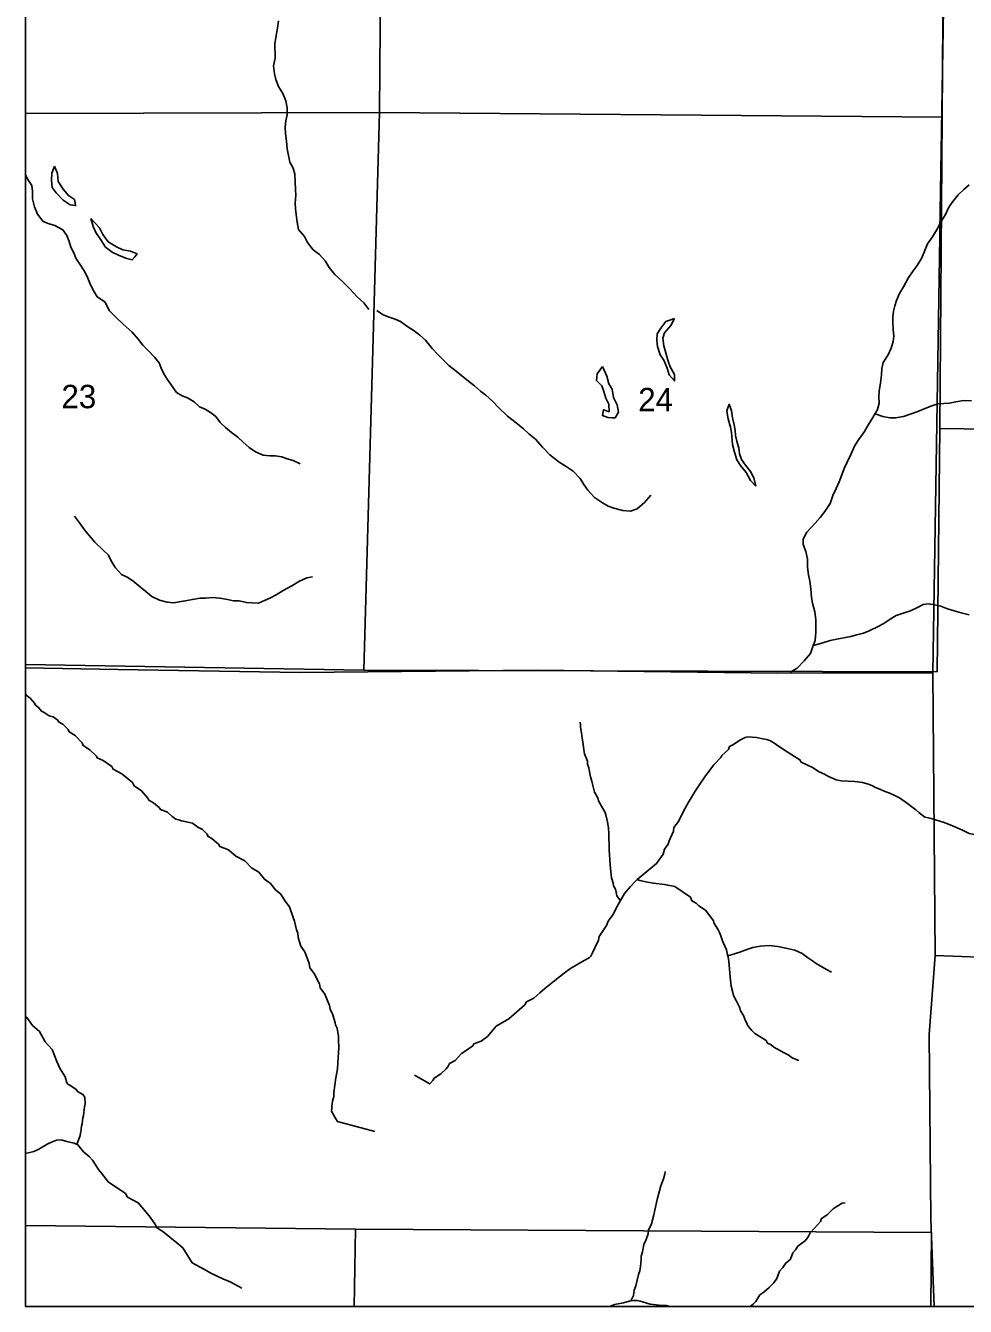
# Model space of a CAD drawing. Extents: x -10 to 158, y 8 to 33.
# Drawn here: x -9.564 to -7.882, y 8.322 to 10.614 of the extents above; entities that cross this region are included whole.
import ezdxf

# ---------------------------------------------------------------- set-up
doc = ezdxf.new("R2010")
doc.units = 0
for name, color, linetype in [('GM_X_Corporation', 7, 'Continuous'), ('GM_X_Minor_Lake', 7, 'Continuous'), ('GM_X_Minor_River', 7, 'Continuous'), ('GM_X_Section_Text', 7, 'Continuous')]:
    doc.layers.add(name, color=color, linetype=linetype)

msp = doc.modelspace()

# ---------------------------------------------------------------- linework, layer by layer
at = {"layer": 'GM_X_Corporation'}
for points in [[(-3.9824, 15.1217), (-9.5644, 15.1217), (-9.5644, 9.4643), (-9.3995, 9.4613), (-9.0726, 9.4561), (-8.6489, 9.4603), (-8.2177, 9.4548), (-7.9405, 9.4552), (-7.9359, 8.9497), (-7.8105, 8.9446), (-6.576, 8.9279), (-5.6716, 8.9116)], [(-3.9824, 15.1217), (-7.9061, 15.1217), (-7.9061, 14.9456), (-7.9061, 14.9432), (-7.9044, 14.3264), (-7.9089, 13.4536), (-7.9163, 10.9342), (-7.9163, 10.9333), (-7.9276, 10.245), (-7.9277, 10.2365), (-7.9405, 9.4552), (-7.9359, 8.9497), (-7.8105, 8.9446), (-6.576, 8.9279), (-5.6716, 8.9116)]]:
    msp.add_lwpolyline(points, dxfattribs=at)
for points in [[(-7.9061, 15.1217), (-9.5644, 15.1217), (-9.5644, 9.4643), (-9.3995, 9.4613), (-9.0726, 9.4561), (-8.6489, 9.4603), (-8.2177, 9.4548), (-7.9405, 9.4552), (-7.9277, 10.2365), (-7.9276, 10.245), (-7.9163, 10.9333), (-7.9163, 10.9342), (-7.9089, 13.4536), (-7.9044, 14.3264), (-7.9061, 14.9432), (-7.9061, 14.9456)], [(-9.5644, 11.46), (-9.5644, 10.4563), (-8.9307, 10.4584), (-8.9234, 11.4538)], [(-7.9172, 11.45), (-7.9205, 10.8845), (-7.9238, 10.4498), (-8.9307, 10.4584), (-8.9234, 11.4538)], [(-7.0512, 10.8902), (-7.0611, 9.881), (-7.9279, 9.893), (-7.9238, 10.4498), (-7.9205, 10.8845)], [(-9.5644, 10.4563), (-9.5644, 9.4706), (-8.9587, 9.4604), (-8.9307, 10.4584)], [(-7.9238, 10.4498), (-7.9279, 9.893), (-7.9324, 9.4573), (-8.9587, 9.4604), (-8.9307, 10.4584)], [(-9.5644, 9.4643), (-9.5644, 8.3217), (-3.0592, 8.3217), (-3.0461, 8.849), (-3.0384, 9.32), (-3.038, 9.8353), (-3.5382, 9.8396), (-4.0418, 9.845), (-4.0443, 9.3749), (-4.0456, 9.0756), (-4.0474, 8.8852), (-4.2975, 8.8883), (-4.8083, 8.897), (-5.5966, 8.9104), (-5.6716, 8.9116), (-6.576, 8.9279), (-7.8105, 8.9446), (-7.9359, 8.9497), (-7.9405, 9.4552), (-8.2177, 9.4548), (-8.6489, 9.4603), (-9.0726, 9.4561), (-9.3995, 9.4613)], [(-7.9379, 8.3217), (-3.0592, 8.3217), (-3.0461, 8.849), (-3.0384, 9.32), (-3.038, 9.8353), (-3.5382, 9.8396), (-4.0418, 9.845), (-4.0443, 9.3749), (-4.0456, 9.0756), (-4.0474, 8.8852), (-4.2975, 8.8883), (-4.8083, 8.897), (-5.5966, 8.9104), (-5.6716, 8.9116), (-6.576, 8.9279), (-7.8105, 8.9446), (-7.9359, 8.9497), (-7.947, 8.8081), (-7.9441, 8.4785)], [(-9.5644, 9.4643), (-9.5644, 8.3217), (-7.9379, 8.3217), (-7.9441, 8.4785), (-7.947, 8.8081), (-7.9359, 8.9497), (-7.9405, 9.4552), (-8.2177, 9.4548), (-8.6489, 9.4603), (-9.0726, 9.4561), (-9.3995, 9.4613)], [(-9.5644, 8.4667), (-9.5644, 8.3217), (-8.9763, 8.3217), (-8.9739, 8.4602)], [(-8.9763, 8.3217), (-7.9439, 8.3217), (-7.9427, 8.454), (-8.9739, 8.4602)]]:
    msp.add_lwpolyline(points, close=True, dxfattribs=at)
at = {"layer": 'GM_X_Minor_Lake'}
for points in [[(-9.5126, 10.3624), (-9.5174, 10.3494), (-9.518, 10.3373), (-9.5171, 10.324), (-9.5098, 10.3142), (-9.4971, 10.3015), (-9.4845, 10.2929), (-9.475, 10.2915), (-9.4758, 10.2963)], [(-9.4758, 10.2963), (-9.4767, 10.3025), (-9.4878, 10.3096), (-9.4974, 10.3212), (-9.5062, 10.3348), (-9.5072, 10.3488), (-9.5126, 10.3624)], [(-9.4479, 10.2683), (-9.4435, 10.2543), (-9.4389, 10.2437), (-9.43, 10.2301), (-9.4211, 10.2173), (-9.4096, 10.208), (-9.3967, 10.2021), (-9.3834, 10.1969), (-9.3735, 10.1943), (-9.3688, 10.2001)], [(-9.3688, 10.2001), (-9.3649, 10.2051), (-9.3767, 10.2099), (-9.3904, 10.2124), (-9.4018, 10.2179), (-9.4163, 10.2269), (-9.4259, 10.2397), (-9.4321, 10.2521), (-9.4479, 10.2683)], [(-8.4025, 10.0898), (-8.418, 10.0839), (-8.4273, 10.0724), (-8.434, 10.0624), (-8.4342, 10.0503), (-8.4333, 10.0393), (-8.4282, 10.0245), (-8.4216, 10.0147), (-8.4161, 10.0004), (-8.4126, 9.989), (-8.4029, 9.9778), (-8.4028, 9.9857)], [(-8.4028, 9.9857), (-8.4027, 9.9895), (-8.4108, 10.0031), (-8.4148, 10.0152), (-8.4184, 10.0284), (-8.422, 10.0409), (-8.4237, 10.0542), (-8.4204, 10.0637), (-8.4092, 10.0768), (-8.4025, 10.0898)], [(-8.5315, 10.0038), (-8.5412, 9.9908), (-8.5426, 9.9786), (-8.5326, 9.9693), (-8.529, 9.959), (-8.5258, 9.9469), (-8.5204, 9.936), (-8.5198, 9.9227), (-8.5297, 9.9264), (-8.5319, 9.9157), (-8.522, 9.9121), (-8.5145, 9.9117)], [(-8.5145, 9.9117), (-8.509, 9.9115), (-8.5031, 9.9218), (-8.5052, 9.9351), (-8.5118, 9.9479), (-8.5143, 9.963), (-8.5205, 9.9728), (-8.5241, 9.9861), (-8.5315, 10.0038)], [(-8.3076, 9.9278), (-8.3089, 9.9239), (-8.3068, 9.9099), (-8.3024, 9.8948), (-8.3008, 9.8853), (-8.299, 9.8641), (-8.2954, 9.8501), (-8.291, 9.8364), (-8.2848, 9.8267), (-8.2744, 9.8139), (-8.2667, 9.7999), (-8.2574, 9.7898)], [(-8.2574, 9.7898), (-8.261, 9.8042), (-8.2665, 9.8155), (-8.2757, 9.8272), (-8.2827, 9.8373), (-8.2863, 9.8471), (-8.2875, 9.8574), (-8.2911, 9.8699), (-8.2935, 9.8801), (-8.2944, 9.8899), (-8.296, 9.8994), (-8.2989, 9.9115), (-8.3009, 9.9244), (-8.3049, 9.9361), (-8.3076, 9.9278)]]:
    msp.add_lwpolyline(points, dxfattribs=at)
at = {"layer": 'GM_X_Minor_River'}
for points in [[(-8.9497, 10.1058), (-8.959, 10.1173), (-8.9709, 10.1286), (-8.9839, 10.1425), (-8.9966, 10.1552), (-9.0111, 10.1683), (-9.0208, 10.1811), (-9.0281, 10.1928), (-9.0385, 10.2041), (-9.0496, 10.2123), (-9.0599, 10.2258), (-9.0654, 10.2364), (-9.0758, 10.2488), (-9.0782, 10.2621), (-9.0802, 10.2757), (-9.0811, 10.2859), (-9.0816, 10.2962), (-9.0806, 10.3102), (-9.0815, 10.3201), (-9.0817, 10.3349), (-9.0826, 10.3481), (-9.0857, 10.3587), (-9.0911, 10.3693), (-9.0936, 10.381), (-9.096, 10.3931), (-9.0973, 10.4071), (-9.0989, 10.4204), (-9.0998, 10.4318), (-9.0984, 10.4432), (-9.0963, 10.4538), (-9.096, 10.4663), (-9.0985, 10.4792), (-9.1039, 10.4924), (-9.1116, 10.5049), (-9.1167, 10.5173), (-9.1191, 10.5272), (-9.1204, 10.5416), (-9.1179, 10.5556), (-9.1182, 10.581), (-9.1157, 10.5959), (-9.1136, 10.6092), (-9.1118, 10.6221)], [(-9.0726, 9.8296), (-9.0855, 9.8352), (-9.0961, 9.8385), (-9.1056, 9.8418), (-9.1174, 9.844), (-9.1269, 9.8439), (-9.139, 9.8449), (-9.1527, 9.8508), (-9.1642, 9.859), (-9.1749, 9.868), (-9.1845, 9.877), (-9.196, 9.8856), (-9.2063, 9.8942), (-9.2159, 9.9032), (-9.2236, 9.9141), (-9.2331, 9.9212), (-9.2431, 9.9272), (-9.2533, 9.9316), (-9.2629, 9.9406), (-9.2744, 9.9473), (-9.2843, 9.951), (-9.2942, 9.957), (-9.3008, 9.9668), (-9.3108, 9.9807), (-9.3169, 9.9905), (-9.3216, 10.0007), (-9.3251, 10.0105), (-9.3336, 10.0203), (-9.3443, 10.0319), (-9.3543, 10.0417), (-9.3624, 10.0518), (-9.3739, 10.065), (-9.39, 10.0792), (-9.4015, 10.0909), (-9.4145, 10.1032), (-9.4227, 10.1195), (-9.436, 10.1284), (-9.4422, 10.1382), (-9.4484, 10.1499), (-9.4543, 10.165), (-9.4597, 10.1748), (-9.4659, 10.185), (-9.4744, 10.1974), (-9.4783, 10.2072), (-9.4833, 10.217), (-9.4864, 10.2273), (-9.4904, 10.2382), (-9.4977, 10.248), (-9.5118, 10.2558), (-9.5221, 10.2587), (-9.5327, 10.2632), (-9.5431, 10.2763), (-9.5482, 10.2896), (-9.5518, 10.3039), (-9.5519, 10.3176), (-9.5535, 10.3278), (-9.5605, 10.338), (-9.5644, 10.346)], [(-8.1956, 9.4569), (-8.1833, 9.4638), (-8.1706, 9.4769), (-8.1594, 9.4903), (-8.155, 9.5025), (-8.151, 9.5132), (-8.1497, 9.5284), (-8.15, 9.5512), (-8.1516, 9.5649), (-8.1556, 9.58), (-8.1577, 9.5902), (-8.159, 9.6058), (-8.1607, 9.6194), (-8.1628, 9.6308), (-8.1645, 9.6444), (-8.1646, 9.6589), (-8.1679, 9.6725), (-8.1722, 9.685), (-8.1727, 9.6948), (-8.1657, 9.7074), (-8.1511, 9.7232), (-8.1421, 9.7336), (-8.1335, 9.7443), (-8.1242, 9.7585), (-8.1191, 9.773), (-8.1136, 9.7856), (-8.1077, 9.7974), (-8.1033, 9.81), (-8.0989, 9.8211), (-8.0944, 9.8314), (-8.0871, 9.8463), (-8.0797, 9.862), (-8.0734, 9.8723), (-8.0629, 9.8872), (-8.0574, 9.8968), (-8.0477, 9.9121), (-8.0392, 9.9267), (-8.0363, 9.9381), (-8.0368, 9.9495), (-8.0366, 9.9594), (-8.0337, 9.9746), (-8.0324, 9.989), (-8.0318, 10), (-8.0293, 10.0107), (-8.0203, 10.0245), (-8.0148, 10.0363), (-8.0115, 10.0482), (-8.0102, 10.0577), (-8.0111, 10.0702), (-8.012, 10.0823), (-8.0117, 10.0922), (-8.0107, 10.1025), (-8.0082, 10.112), (-8.0053, 10.1219), (-7.9998, 10.1341), (-7.9927, 10.146), (-7.9846, 10.1617), (-7.9753, 10.1747), (-7.9686, 10.1843), (-7.96, 10.1984), (-7.9549, 10.2114), (-7.9501, 10.2229), (-7.9408, 10.2359), (-7.9319, 10.2508), (-7.926, 10.2627), (-7.9185, 10.2745), (-7.9115, 10.289), (-7.9044, 10.299), (-7.8947, 10.3109), (-7.885, 10.3205), (-7.8752, 10.329)], [(-8.9357, 10.104), (-8.9254, 10.0967), (-8.9155, 10.0926), (-8.9029, 10.0882), (-8.8934, 10.0842), (-8.8804, 10.0749), (-8.8708, 10.0689), (-8.8585, 10.06), (-8.8485, 10.0506), (-8.8366, 10.0359), (-8.8266, 10.0251), (-8.8066, 10.0056), (-8.7939, 9.9955), (-8.7832, 9.9869), (-8.7717, 9.9775), (-8.761, 9.9693), (-8.7502, 9.9596), (-8.7406, 9.9525), (-8.728, 9.9409), (-8.7187, 9.9311), (-8.7015, 9.9147), (-8.6865, 9.9031), (-8.6731, 9.8919), (-8.6635, 9.8833), (-8.6516, 9.8735), (-8.6393, 9.8593), (-8.6262, 9.8458), (-8.6093, 9.8327), (-8.5982, 9.826), (-8.5841, 9.8163), (-8.5717, 9.8032), (-8.5652, 9.7923), (-8.5578, 9.7825), (-8.5459, 9.769), (-8.5317, 9.7597), (-8.5214, 9.7537), (-8.5115, 9.7501), (-8.4955, 9.7461), (-8.4814, 9.7447), (-8.4694, 9.7487), (-8.4566, 9.7603), (-8.445, 9.7737)], [(-8.0437, 9.9189), (-8.0299, 9.9139), (-8.0173, 9.9118), (-8.0071, 9.9115), (-7.9927, 9.914), (-7.981, 9.9183), (-7.9674, 9.923), (-7.9531, 9.9289), (-7.9421, 9.9332), (-7.9315, 9.9368), (-7.9209, 9.9373), (-7.9103, 9.9382), (-7.899, 9.9406), (-7.8853, 9.9427), (-7.8709, 9.9421)], [(-9.051, 9.6271), (-9.0607, 9.6253), (-9.0739, 9.6195), (-9.0878, 9.6114), (-9.1033, 9.6029), (-9.1157, 9.5951), (-9.127, 9.5893), (-9.1368, 9.5847), (-9.1474, 9.5804), (-9.1591, 9.5806), (-9.169, 9.5813), (-9.1823, 9.5842), (-9.1922, 9.5844), (-9.2032, 9.5866), (-9.2165, 9.5891), (-9.2298, 9.5905), (-9.2423, 9.5892), (-9.2517, 9.5891), (-9.2657, 9.587), (-9.2786, 9.5842), (-9.2892, 9.5826), (-9.299, 9.5806), (-9.3108, 9.582), (-9.3245, 9.5853), (-9.3386, 9.5919), (-9.3489, 9.6009), (-9.3585, 9.6088), (-9.3726, 9.62), (-9.3826, 9.6264), (-9.3925, 9.6312), (-9.4032, 9.6432), (-9.4106, 9.6549), (-9.416, 9.6658), (-9.4263, 9.6756), (-9.4405, 9.6891), (-9.4505, 9.7011), (-9.459, 9.7116), (-9.4682, 9.7241), (-9.4767, 9.7361)], [(-8.1542, 9.5046), (-8.1357, 9.5096), (-8.124, 9.5132), (-8.1093, 9.5164), (-8.0968, 9.5189), (-8.0869, 9.5205), (-8.0764, 9.5233), (-8.0646, 9.5265), (-8.0544, 9.5304), (-8.0394, 9.5375), (-8.0281, 9.5437), (-8.0164, 9.5518), (-8.0062, 9.558), (-7.9919, 9.5628), (-7.9802, 9.5667), (-7.9677, 9.5726), (-7.9576, 9.578), (-7.9481, 9.5789), (-7.9367, 9.5771), (-7.926, 9.5746), (-7.9142, 9.5702), (-7.902, 9.5662), (-7.8895, 9.5626), (-7.875, 9.5593)], [(-8.9392, 8.6344), (-9.006, 8.6523), (-9.0106, 8.6606), (-9.017, 8.6708), (-9.0164, 8.6765), (-9.0164, 8.6796), (-9.0151, 8.6887), (-9.0129, 8.6975), (-9.0127, 8.7047), (-9.009, 8.731), (-9.0058, 8.747), (-9.0056, 8.7576), (-9.0038, 8.785), (-9.004, 8.7979), (-9.0045, 8.8048), (-9.0067, 8.8195), (-9.0095, 8.8256), (-9.0103, 8.829), (-9.0143, 8.8434), (-9.019, 8.8535), (-9.0203, 8.8604), (-9.0286, 8.8807), (-9.0372, 8.892), (-9.0384, 8.8992), (-9.0479, 8.9173), (-9.0556, 8.9278), (-9.0569, 8.9354), (-9.0645, 8.9562), (-9.0715, 8.9663), (-9.0763, 8.9818), (-9.0772, 8.9898), (-9.0792, 8.9958), (-9.0829, 9.011), (-9.0853, 9.0174), (-9.0921, 9.037), (-9.0998, 9.0468), (-9.1073, 9.0596), (-9.1173, 9.0674), (-9.1258, 9.0787), (-9.137, 9.0861), (-9.147, 9.0988), (-9.1601, 9.1066), (-9.1721, 9.119), (-9.1882, 9.1271), (-9.2009, 9.1387), (-9.2169, 9.1449), (-9.2189, 9.1486), (-9.2305, 9.1583), (-9.2381, 9.1631), (-9.2393, 9.1665), (-9.2475, 9.1751), (-9.2559, 9.1792), (-9.2655, 9.1863), (-9.2823, 9.1902), (-9.2857, 9.1905), (-9.2884, 9.1916), (-9.2952, 9.1938), (-9.3021, 9.1986), (-9.3102, 9.2064), (-9.3232, 9.2112), (-9.3252, 9.2142), (-9.3356, 9.2228), (-9.344, 9.2276), (-9.3456, 9.231), (-9.3572, 9.2445), (-9.3703, 9.253), (-9.373, 9.259), (-9.3919, 9.2747), (-9.4076, 9.2828), (-9.41, 9.2877), (-9.4254, 9.2985), (-9.4361, 9.3032), (-9.4376, 9.3063), (-9.4492, 9.3175), (-9.4611, 9.3253), (-9.4631, 9.3302), (-9.4755, 9.3433), (-9.4866, 9.3499), (-9.4882, 9.3541), (-9.4978, 9.3634), (-9.5055, 9.3679), (-9.5067, 9.3705), (-9.5148, 9.3765), (-9.522, 9.3786), (-9.5309, 9.3846), (-9.5362, 9.3868), (-9.5413, 9.3935), (-9.5466, 9.3976), (-9.5478, 9.4006), (-9.5564, 9.4104), (-9.5633, 9.4156), (-9.5644, 9.4187)], [(-8.4996, 9.0477), (-8.5058, 9.0564), (-8.5074, 9.0632), (-8.5083, 9.0681), (-8.5118, 9.0745), (-8.5126, 9.079), (-8.5154, 9.0888), (-8.5181, 9.1111), (-8.5186, 9.1214), (-8.5197, 9.1388), (-8.5206, 9.1679), (-8.5211, 9.1774), (-8.5225, 9.1891), (-8.5257, 9.2016), (-8.5266, 9.2057), (-8.5312, 9.2128), (-8.539, 9.2264), (-8.5403, 9.2316), (-8.5457, 9.2418), (-8.5498, 9.2561), (-8.5506, 9.2614), (-8.5534, 9.2693), (-8.5555, 9.2818), (-8.5563, 9.2855), (-8.5583, 9.2919), (-8.5588, 9.2976), (-8.5636, 9.3108), (-8.5649, 9.3176), (-8.5657, 9.3233), (-8.5662, 9.3274), (-8.5687, 9.3433), (-8.5692, 9.3482), (-8.5704, 9.3543), (-8.5709, 9.3596), (-8.5709, 9.3633), (-8.5714, 9.3671)], [(-8.4686, 9.0853), (-8.4695, 9.0855), (-8.4348, 9.1142), (-8.423, 9.1311), (-8.4209, 9.1398), (-8.4142, 9.149), (-8.4124, 9.1547), (-8.4048, 9.1719), (-8.4037, 9.1784), (-8.3956, 9.1895), (-8.389, 9.2033), (-8.3835, 9.2133), (-8.3784, 9.2228), (-8.3729, 9.2316), (-8.3655, 9.2439), (-8.3577, 9.2562), (-8.3485, 9.2696), (-8.3418, 9.2784), (-8.3322, 9.2911), (-8.3199, 9.3038), (-8.3181, 9.3073), (-8.3058, 9.3181), (-8.3044, 9.3238), (-8.2972, 9.3274), (-8.2856, 9.3348), (-8.2808, 9.3375), (-8.2763, 9.3399), (-8.2713, 9.3407), (-8.2558, 9.3395), (-8.2448, 9.3374), (-8.2376, 9.336), (-8.2311, 9.3339), (-8.2234, 9.3291), (-8.2184, 9.3254), (-8.2008, 9.314), (-8.1878, 9.3059), (-8.1782, 9.3), (-8.1759, 9.2958), (-8.156, 9.2863), (-8.1438, 9.2786), (-8.1342, 9.2739), (-8.127, 9.2702), (-8.1189, 9.2662), (-8.1132, 9.264), (-8.1045, 9.2623), (-8.092, 9.2614), (-8.0798, 9.2608), (-8.0662, 9.2592), (-8.0555, 9.2563), (-8.0483, 9.2531), (-8.0429, 9.2505), (-8.0353, 9.2472), (-8.0273, 9.244), (-8.0189, 9.2407), (-8.0093, 9.2363), (-7.9998, 9.2316), (-7.9856, 9.2216), (-7.9779, 9.2157), (-7.971, 9.2101), (-7.9652, 9.2053), (-7.9549, 9.1971), (-7.948, 9.1958), (-7.9435, 9.1949)], [(-7.9435, 9.1949), (-7.9221, 9.1881), (-7.9122, 9.1844), (-7.9011, 9.1797), (-7.887, 9.1741), (-7.8755, 9.1682), (-7.866, 9.1661), (-7.8565, 9.1628), (-7.8439, 9.1591), (-7.8325, 9.1559), (-7.8207, 9.1537), (-7.8082, 9.1509), (-7.7979, 9.1483), (-7.788, 9.1454), (-7.775, 9.1418), (-7.764, 9.137), (-7.7521, 9.1296), (-7.7426, 9.1259), (-7.7323, 9.1253), (-7.7224, 9.1231)], [(-8.868, 8.7354), (-8.8408, 8.7199), (-8.8352, 8.7257), (-8.833, 8.7302), (-8.821, 8.7377), (-8.8117, 8.7469), (-8.8084, 8.7504), (-8.8055, 8.7561), (-8.7957, 8.762), (-8.7842, 8.774), (-8.7793, 8.7775), (-8.764, 8.788), (-8.7618, 8.7914), (-8.749, 8.7962), (-8.7377, 8.8044), (-8.7307, 8.8124), (-8.7218, 8.8232), (-8.6993, 8.8365), (-8.6709, 8.8613), (-8.6676, 8.8666), (-8.6545, 8.8733), (-8.644, 8.8826), (-8.6347, 8.8907), (-8.6261, 8.8977), (-8.6168, 8.9051), (-8.6086, 8.9117), (-8.6, 8.9183), (-8.5929, 8.9233), (-8.5869, 8.9276), (-8.582, 8.9303), (-8.5756, 8.9343), (-8.5644, 8.9409), (-8.5557, 8.9456), (-8.5524, 8.9487), (-8.5498, 8.9544), (-8.5451, 8.9636), (-8.5389, 8.977), (-8.5375, 8.9838), (-8.5242, 9.0034), (-8.5217, 9.011), (-8.518, 9.016), (-8.512, 9.0241), (-8.5073, 9.0344), (-8.5018, 9.044), (-8.497, 9.052), (-8.4922, 9.0604), (-8.4818, 9.0731), (-8.474, 9.0816), (-8.4695, 9.0855), (-8.465, 9.0841), (-8.4509, 9.0809), (-8.4406, 9.0788), (-8.4209, 9.0769), (-8.4019, 9.0731), (-8.3743, 9.0542), (-8.3715, 9.0475), (-8.3639, 9.0431), (-8.3593, 9.0386), (-8.347, 9.0305), (-8.3431, 9.0256), (-8.3331, 9.0118), (-8.3322, 9.008), (-8.328, 9.0016), (-8.3248, 8.9953), (-8.3225, 8.9908), (-8.3197, 8.9851), (-8.3169, 8.9757), (-8.3153, 8.9719), (-8.3098, 8.9599), (-8.3078, 8.9508), (-8.3069, 8.9471), (-8.3057, 8.9388), (-8.3043, 8.9255), (-8.3029, 8.9111), (-8.3015, 8.8945), (-8.2983, 8.8832), (-8.2974, 8.8779), (-8.2923, 8.8689), (-8.2857, 8.8561), (-8.2844, 8.8508), (-8.2794, 8.8422), (-8.2754, 8.8328), (-8.2734, 8.8283), (-8.2722, 8.8249), (-8.2688, 8.8204), (-8.2645, 8.8152), (-8.2587, 8.81), (-8.2384, 8.7975), (-8.2365, 8.7926), (-8.2296, 8.7897), (-8.225, 8.7856), (-8.2062, 8.7753), (-8.1994, 8.7717), (-8.1921, 8.7665), (-8.1879, 8.765), (-8.1803, 8.7618)], [(-8.3073, 8.9488), (-8.2878, 8.955), (-8.2716, 8.961), (-8.2625, 8.9642), (-8.2497, 8.9663), (-8.2334, 8.9674), (-8.2179, 8.9657), (-8.2034, 8.963), (-8.1871, 8.9591), (-8.1745, 8.9533), (-8.1645, 8.9462), (-8.1557, 8.94), (-8.1492, 8.9351), (-8.1304, 8.9245), (-8.122, 8.9197)], [(-9.4727, 8.6117), (-9.4665, 8.6273), (-9.4662, 8.6315), (-9.4651, 8.6368), (-9.4652, 8.6398), (-9.4645, 8.6444), (-9.4634, 8.6482), (-9.4617, 8.6589), (-9.4607, 8.6635), (-9.4587, 8.6791), (-9.458, 8.6844), (-9.4582, 8.6962), (-9.4617, 8.7011), (-9.4713, 8.7062), (-9.4736, 8.71), (-9.4851, 8.7178), (-9.4886, 8.7192), (-9.4905, 8.7219), (-9.4938, 8.7328), (-9.5027, 8.7471), (-9.5083, 8.76), (-9.517, 8.7815), (-9.5294, 8.795), (-9.5396, 8.8138), (-9.5523, 8.8246), (-9.562, 8.8385), (-9.5644, 8.84)], [(-9.1773, 8.3543), (-9.197, 8.3652), (-9.2054, 8.3685), (-9.2104, 8.3703), (-9.2326, 8.3813), (-9.2444, 8.3876), (-9.2663, 8.3998), (-9.2827, 8.4265), (-9.2939, 8.4355), (-9.3185, 8.4556), (-9.33, 8.4626), (-9.3316, 8.4675), (-9.3417, 8.4814), (-9.346, 8.4875), (-9.3627, 8.5073), (-9.3822, 8.5173), (-9.3857, 8.5237), (-9.4076, 8.5385), (-9.4161, 8.5441), (-9.4285, 8.5602), (-9.4339, 8.5666), (-9.4449, 8.5835), (-9.4503, 8.5892), (-9.4607, 8.5985), (-9.4708, 8.6109), (-9.4773, 8.6138), (-9.4906, 8.617), (-9.5009, 8.6195), (-9.5092, 8.6194), (-9.5183, 8.6158), (-9.5243, 8.6127), (-9.5409, 8.6033), (-9.5499, 8.599), (-9.5644, 8.5956)], [(-8.485, 8.3307), (-8.485, 8.3307), (-8.4811, 8.3315), (-8.4763, 8.3414), (-8.475, 8.3509), (-8.4717, 8.3585), (-8.4671, 8.3787), (-8.465, 8.3856), (-8.4636, 8.3932), (-8.4633, 8.3992), (-8.4627, 8.4061), (-8.4624, 8.4118), (-8.4603, 8.4194), (-8.4578, 8.4327), (-8.4535, 8.4415), (-8.4502, 8.4514), (-8.4492, 8.4579), (-8.4437, 8.4697), (-8.4398, 8.4853), (-8.4377, 8.4941), (-8.4339, 8.5131), (-8.4271, 8.5375), (-8.4224, 8.5497), (-8.4202, 8.5581), (-8.4192, 8.5634)], [(-8.2673, 8.3217), (-8.2621, 8.3259), (-8.2569, 8.3306), (-8.2502, 8.3421), (-8.2431, 8.3471), (-8.2334, 8.3557), (-8.229, 8.3595), (-8.2252, 8.3641), (-8.2197, 8.3714), (-8.2146, 8.3848), (-8.2087, 8.3913), (-8.2043, 8.3986), (-8.1949, 8.406), (-8.1909, 8.4174), (-8.1861, 8.4228), (-8.1817, 8.4294), (-8.1682, 8.4398), (-8.1634, 8.4464), (-8.1598, 8.4533), (-8.1523, 8.4617), (-8.1412, 8.4737), (-8.1394, 8.479), (-8.1293, 8.4856), (-8.1188, 8.4961), (-8.1136, 8.4999), (-8.1024, 8.5066), (-8.0974, 8.5071)], [(-8.5188, 8.3217), (-8.5101, 8.3252), (-8.4939, 8.3282), (-8.4837, 8.331), (-8.4766, 8.3323), (-8.4694, 8.3321), (-8.4644, 8.331), (-8.4602, 8.3296), (-8.4461, 8.3256), (-8.4302, 8.324), (-8.4173, 8.3231), (-8.4099, 8.3217)]]:
    msp.add_lwpolyline(points, dxfattribs=at)

# ---------------------------------------------------------------- texts
at = {"layer": 'GM_X_Section_Text'}
for s, p in [('23', (-9.5002, 9.929)), ('24', (-8.4677, 9.9235))]:
    msp.add_text(s, height=0.04186, rotation=0, dxfattribs=at).set_placement(p)

doc.saveas('drawing.dxf')
